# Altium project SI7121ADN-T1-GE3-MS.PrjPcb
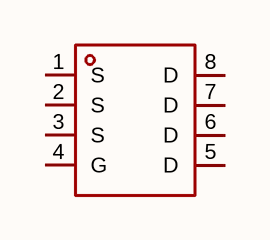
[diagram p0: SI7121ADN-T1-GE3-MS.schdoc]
1 sheet, 1 parts. Net scope: global (net labels, ports and power ports of the same name join across sheets).

## Sheet SI7121ADN-T1-GE3-MS.schdoc
size 127 x 101 mm

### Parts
Q?  si7121adn-t1-ge3-ms  [POWERPAK-1212-8_L3.0-W3.0-P0.65-LS3.3-BL]  (value not drawn)

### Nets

Not connected (* = marked no-connect by the designer): Q? 1(S) 2(S) 3(S) 4(G) 5(D) 6(D) 7(D) 8(D)

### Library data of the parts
Q? = si7121adn-t1-ge3-ms: 数量:1个P沟道;漏源电压(Vdss):30V;连续漏极电流(Id):35A;导通电阻(RDS(on)):12mΩ@10V;耗散功率(Pd):15W;阈值电压(Vgs(th)):1.6V;; Manufacturer: MSKSEMI(美森科); AddInBom: yes; ModelId: 74fc8db97a8d4d328d7f3b4acba39a5e; ModelTransform: 129.921,129.921,0,0,0,0,0,0,0; Number: 1个P沟道; Drain to Source Voltage: 30V; Current - Continuous Drain(Id): 35A; Pd - Power Dissipation: 15W; Gate Threshold Voltage (Vgs(th)): 1.6V; Gate Charge(Qg): 22nC; Input Capacitance(Ciss): 1.33nF; Reverse Transfer Capacitance (Crss@Vds): 156pF; Type: P沟道; Output Capacitance(Coss): 183pF; Vgs: ±20V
